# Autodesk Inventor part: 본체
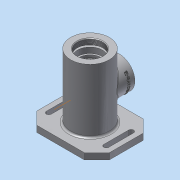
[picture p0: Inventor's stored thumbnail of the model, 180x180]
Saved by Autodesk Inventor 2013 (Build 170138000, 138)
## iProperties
Created: 2017-10
Part Number: 본체
Material: 알루미늄 6061
Document SubType Name: Modeling
Designer: dgall
Mass: 740.706 g
Surface Area: 652.711 cm^2
Volume: 273.323 cm^3
Density: 2.71 g/cm^3
Author: dgall
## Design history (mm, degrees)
sketch "스케치1"
  geometry: C1 r 31 at (0, 0); 1 further point
  constraints: 1 centre point, 1 coincident
  dimensions: "d0" = 62 diameter of C1
extrude "돌출1" new body sketch "스케치1" distance "d1" = 102; taper "d2" = 0 deg
sketch "스케치2"
  geometry: L1 (-58, 47)-(58, 47); L2 (58, 47)-(58, -47); L3 (58, -47)-(-58, -47); L4 (-58, -47)-(-58, 47); C1 r 31 at (0, 0) reference; C2 r 35 at (0, 0); 2 further points
  constraints: 8 end point, 2 midpoint, 2 parallel, 1 centre point, 1 coincident, 1 horizontal, 1 horizontal alignment, 1 perpendicular, 1 vertical alignment
  dimensions: "d3" = 94 distance of L1.end L2.end; "d5" = 116 distance of L2.end L3.end; "d6" = 70 diameter of C2
extrude "돌출2" join sketch "스케치2" distance "d7" = 10; taper "d8" = 0 deg
extrude "돌출3" join sketch "스케치2" distance "d9" = 13; taper "d10" = 0 deg
chamfer "모따기1" distance "d11" = 20; stored, may be unused: second distance "d12" = 2, angle "d13" = 45 deg
sketch "스케치3"
  geometry: L1 (31, 102)-(-31, 102) reference; L2 (-31, 0)-(31, 0) reference; L3 (-35, -13)-(35, -13) reference; L4 (35, -10)-(-35, -10) reference; L5 (47, -10)-(27, -10) reference; L6 (27, -10)-(27, 0) reference; L7 (27, 0)-(47, 0) reference; L8 (47, 0)-(47, -10) reference; L9 (27, -10)-(27, 0) reference; L10 (-27, -10)-(27, -10) reference; L11 (-27, 0)-(-27, -10) reference; L12 (27, 0)-(-27, 0) reference; L13 (-27, -10)-(-47, -10) reference; L14 (-47, -10)-(-47, 0) reference; L15 (-47, 0)-(-27, 0) reference; L16 (-27, 0)-(-27, -10) reference; L17 (31, 0)-(31, 102) reference; L18 (-31, 0)-(-31, 102) reference; L19 (31, 71)-(47, 71); L20 (47, 71)-(47, 21); L21 (47, 21)-(31, 21); L22 (31, 71)-(18, 71); L23 (18, 71)-(18, 21); L24 (18, 21)-(31, 21); L25 (47, 46)-(18, 46); 1 further point
  constraints: 14 end point, 4 perpendicular, 2 midpoint, 2 parallel, 2 point on line
  dimensions: "d14" = 56 distance from line of L1 L25.start; "d15" = 50 distance of L19.end L20.end; "d16" = 47 distance from line of point (0, 0) L20; "d17" = 13 distance of L23.end L21.end
revolve "회전1" sketch "스케치3" stored, may be unused: angle "d18" = 90 deg
sketch "스케치4"
  geometry: L1 (47, -10)-(27, -10) reference; L2 (27, -10)-(27, 0) reference; L3 (27, 0)-(47, 0) reference; L4 (47, 0)-(47, -10) reference; L5 (27, -10)-(27, 0) reference; L6 (-27, -10)-(27, -10) reference; L7 (-27, 0)-(-27, -10) reference; L8 (27, 0)-(-27, 0) reference; L9 (-27, -10)-(-47, -10) reference; L10 (-47, -10)-(-47, 0) reference; L11 (-47, 0)-(-27, 0) reference; L12 (-27, 0)-(-27, -10) reference; L13 (31, 102)-(-31, 102) reference; L14 (31, 0)-(31, 102) reference; L15 (-31, 0)-(-31, 102) reference; L16 (31, 71)-(47, 71) reference; L17 (47, 21)-(47, 71) reference; L18 (31, 21)-(47, 21) reference; L19 (12.904, 1)-(12.5, 1.7); L20 (12.5, 1.7)-(12.5, 8.3); L21 (12.5, 8.3)-(10, 8.3); L22 (10, 8.3)-(10, 11); L23 (10, 11)-(16.5, 11); L24 (16.5, 11)-(16.5, 16); L25 (16.5, 16)-(17.5, 16); L26 (17.5, 16)-(17.5, 27); L27 (17.5, 27)-(26, 27); L28 (26, 27)-(26, 65); L29 (26, 65)-(17.5, 65); L30 (17.5, 65)-(17.5, 76); L31 (17.5, 76)-(18.5, 76); L32 (18.5, 76)-(18.5, 77.75); L33 (18.5, 77.75)-(17.5, 77.75); L34 (17.5, 77.75)-(17.5, 81); L35 (17.5, 81)-(20, 81); L36 (20, 81)-(20, 90); L37 (20, 90)-(24, 90); L38 (24, 90)-(24, 93); L39 (24, 93)-(0, 93); L40 (0, 93)-(0, -13); L41 (-35, -13)-(35, -13) reference; L42 (12.904, 1)-(16, 1); L43 (16, 1)-(22, -13); L44 (22, -13)-(0, -13); 2 further points
  constraints: 50 end point, 11 parallel, 11 perpendicular, 1 midpoint, 1 point on line, 1 vertical alignment
  dimensions: "d31" = 25 diameter of L20 L40; "d32" = 20 diameter of L22 L40; "d34" = 30 deg angle of L20 L19; "d35" = 7.3 vertical distance of L19.start L20.end; "d36" = 2.7 distance between parallel lines of L23 L21; "d37" = 24 distance between parallel lines of L41 L23; "d38" = 5 distance of L23.end L24.end; "d39" = 33 diameter of L24 L40; "d40" = 11 distance of L25.end L26.end; "d41" = 35 diameter of L26 L40; "d42" = 52 diameter of L28 L40; "d43" = 35 diameter of L30 L40; "d44" = 11 distance between parallel lines of L31 L29; "d45" = 26 distance between parallel lines of L13 L31; "d46" = 21 distance between parallel lines of L13 L35; "d47" = 3 distance of L37.end L38.end; "d48" = 12 distance between parallel lines of L13 L37; "d49" = 48 diameter of L38 L40; "d50" = 40 diameter of L36 L40; "d51" = 35 diameter of L34 L40; "d52" = 1.75 distance of L31.end L32.end; "d53" = 37 diameter of L32 L40; "d54" = 32 diameter of L42.end L40; "d55" = 0.7 vertical distance of L19.start L19.end; "d56" = 44 diameter of L43.end L40
revolve "회전2" sketch "스케치4" stored, may be unused: angle "d57" = 90 deg
hole "구멍1" diameter "d60" = 32; stored, may be unused: countersink angle "d64" = 90 deg, drill point angle "d66" = 0 deg; dims "d58" = 10, "d59" = 10, "d61" = 6, "d62" = 4, "d63" = 2, "d65" = 47
hole "구멍2" diameter "d69" = 40.376; stored, may be unused: countersink angle "d73" = 90 deg, drill point angle "d75" = 0 deg; dims "d67" = 10, "d68" = 10, "d70" = 9, "d71" = 4, "d72" = 2, "d74" = 9
sketch "스케치5"
  geometry: L1 (38, 47)-(-38, 47) reference; L2 (-50, -20)-(-50, 20); L3 (-42, 20)-(-42, -20); L4 (42, -20)-(42, 20); L5 (50, 20)-(50, -20); C1 r 31 at (0, 0) reference; A1 r 4 centre (-46, 20) between (-42, 20) and (-50, 20); A2 r 4 centre (-46, -20) between (-50, -20) and (-42, -20); A3 r 4 centre (46, 20) between (50, 20) and (42, 20); A4 r 4 centre (46, -20) between (42, -20) and (50, -20)
  constraints: 8 end point, 8 point on circle, 8 tangent, 4 centre point, 3 parallel, 2 horizontal alignment, 1 equal radius, 1 perpendicular
  dimensions: "d76" = 40 distance of A2.centre A1.centre; "d78" = 4 radius of A1; "d79" = 20 vertical distance of A2.centre C1.centre; "d80" = 46 horizontal distance of C1.centre A2.centre; "d81" = 46 horizontal distance of C1.centre A4.centre
extrude "돌출4" cut sketch "스케치5" distance "d82" = 13; taper "d83" = 0 deg
sketch "스케치6"
  geometry: C1 r 16 at (0, 0) reference; 2 further points
  constraints: 1 horizontal alignment
  dimensions: "d84" = 20.5 distance of C1.centre point (-20.5, 0)
hole "구멍3" sketch "스케치6" at (-20.5, 0) diameter "d85" = 2.459; stored, may be unused: countersink angle "d89" = 90 deg, drill point angle "d91" = 0 deg; dims "d86" = 6, "d87" = 4, "d88" = 2, "d90" = 8
fillet "모깎기1" dims "d95" = 0.3
fillet "모깎기2" dims "d96" = 3
fillet "모깎기3" dims "d97" = 3
chamfer "모따기2" distance "d98" = 1; stored, may be unused: second distance "d99" = 2, angle "d100" = 45 deg
chamfer "모따기3" distance "d101" = 1; stored, may be unused: second distance "d102" = 2, angle "d103" = 45 deg
fillet "모깎기4" dims "d104" = 3
fillet "모깎기5" dims "d105" = 3
chamfer "모따기4" distance "d106" = 1; stored, may be unused: second distance "d107" = 2, angle "d108" = 45 deg
node "작업축1"
node "작업 평면1"
node "작업 평면2"
sketch "스케치7"
  geometry: L1 (8, -25)-(8, 25) reference; 3 further points
  constraints: 1 horizontal alignment, 1 midpoint, 1 other
  dimensions: "d109" = 10 distance from line of L1 point (-2, 0)
feature "엠보싱1" sketch "스케치7" dims "d110" = 0.5, "d111" = 0
node "솔리드1"
pattern_circular "원형 패턴1" dims angle "d93" = 360 deg
node "투영된 루프1"
node "투영된 루프2"
node "투영된 루프3"
node "투영된 루프4"
node "투영된 루프5"
node "투영된 루프6"
node "투영된 루프7"
node "투영된 루프8"
